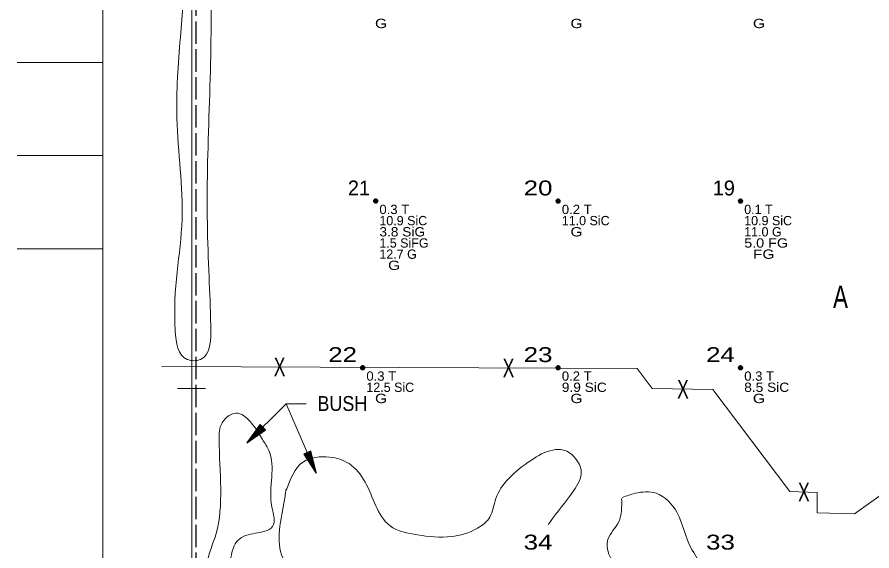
# Model space of a CAD drawing. Extents: x -496 to 480, y -450 to 700.
# Drawn here: x -496.1 to -37.5, y -87.1 to 199.3 of the extents above; entities that cross this region are included whole.
import ezdxf
from ezdxf.enums import TextEntityAlignment as Align

# ---------------------------------------------------------------- set-up
doc = ezdxf.new("R2010")
doc.units = 0
doc.header["$LTSCALE"] = 2
doc.linetypes.add('LONG_DASHED', pattern=[7.5, 6, -1.5])
for name, color, linetype, lineweight in [('1', 7, 'Continuous', 13), ('2', 7, 'Continuous', 35), ('3', 7, 'Continuous', 13), ('4', 7, 'Continuous', 25)]:
    doc.layers.add(name, color=color, linetype=linetype, lineweight=lineweight)

msp = doc.modelspace()

# ---------------------------------------------------------------- linework, layer by layer
at = {"layer": '1'}
for p, q in [((-402.391, 402.339), (-402.391, -402.333)), ((-450.017, 174.973), (-496.057, 174.973)), ((-450.017, 124.973), (-496.057, 124.973)), ((-450.017, 74.973), (-496.057, 74.973)), ((-395.017, -0.027), (-410.017, -0.027))]:
    msp.add_line(p, q, dxfattribs=at)
msp.add_lwpolyline([(449.983, -450.027), (449.983, 399.973), (449.983, 699.973), (-450.017, 699.973), (-450.017, 49.973), (-450.017, -450.027)], dxfattribs=at)
at = {"layer": '2', "linetype": 'LONG_DASHED', "lineweight": 25}
msp.add_line((-400, -400), (-400, 302.339), dxfattribs=at)
at = {"layer": '2'}
for centre in [(-303.709, 100.614), (-205.849, 100.614), (-107.989, 100.614), (-310.699, 11.214), (-205.849, 11.214), (-107.989, 11.214)]:
    msp.add_circle(centre, 1, dxfattribs=at)
for points in [[(-303.72, 101.501), (-302.989, 101.097), (-302.838, 100.248), (-303.523, 99.72), (-304.332, 99.951), (-304.618, 100.709), (-304.371, 101.271), (-303.798, 101.439), (-303.124, 100.945), (-303.141, 100.203), (-303.658, 99.945), (-304.18, 100.114), (-304.405, 100.76), (-303.821, 101.226), (-303.383, 100.692), (-303.422, 100.209), (-304.051, 100.344), (-303.905, 100.979), (-303.613, 100.428)], [(-205.86, 101.501), (-205.129, 101.097), (-204.978, 100.248), (-205.663, 99.72), (-206.472, 99.951), (-206.758, 100.709), (-206.511, 101.271), (-205.938, 101.439), (-205.264, 100.945), (-205.281, 100.203), (-205.798, 99.945), (-206.32, 100.114), (-206.545, 100.76), (-205.961, 101.226), (-205.523, 100.692), (-205.562, 100.209), (-206.191, 100.344), (-206.045, 100.979), (-205.753, 100.428)], [(-108, 101.501), (-107.269, 101.097), (-107.118, 100.248), (-107.803, 99.72), (-108.612, 99.951), (-108.898, 100.709), (-108.651, 101.271), (-108.078, 101.439), (-107.404, 100.945), (-107.421, 100.203), (-107.938, 99.945), (-108.46, 100.114), (-108.685, 100.76), (-108.101, 101.226), (-107.663, 100.692), (-107.702, 100.209), (-108.331, 100.344), (-108.185, 100.979), (-107.893, 100.428)], [(-310.71, 12.101), (-309.979, 11.697), (-309.828, 10.848), (-310.513, 10.32), (-311.322, 10.551), (-311.608, 11.309), (-311.361, 11.871), (-310.788, 12.039), (-310.114, 11.545), (-310.131, 10.803), (-310.648, 10.545), (-311.17, 10.714), (-311.395, 11.36), (-310.811, 11.826), (-310.373, 11.292), (-310.412, 10.809), (-311.041, 10.944), (-310.895, 11.579), (-310.603, 11.028)], [(-205.86, 12.101), (-205.129, 11.697), (-204.978, 10.848), (-205.663, 10.32), (-206.472, 10.551), (-206.758, 11.309), (-206.511, 11.871), (-205.938, 12.039), (-205.264, 11.545), (-205.281, 10.803), (-205.798, 10.545), (-206.32, 10.714), (-206.545, 11.36), (-205.961, 11.826), (-205.523, 11.292), (-205.562, 10.809), (-206.191, 10.944), (-206.045, 11.579), (-205.753, 11.028)], [(-108, 12.101), (-107.269, 11.697), (-107.118, 10.848), (-107.803, 10.32), (-108.612, 10.551), (-108.898, 11.309), (-108.651, 11.871), (-108.078, 12.039), (-107.404, 11.545), (-107.421, 10.803), (-107.938, 10.545), (-108.46, 10.714), (-108.685, 11.36), (-108.101, 11.826), (-107.663, 11.292), (-107.702, 10.809), (-108.331, 10.944), (-108.185, 11.579), (-107.893, 11.028)]]:
    msp.add_spline(points, degree=3, dxfattribs=at)
at = {"layer": '3'}
msp.add_lwpolyline([(-418.392, 11.933), (-163.468, 10.85), (-155.332, 0.015), (-122.789, -0.527), (-81.567, -55.245), (-66.922, -55.787), (-66.922, -66.622), (-46.854, -67.164), (-30.04, -55.245), (79.523, -55.245), (87.202, -45.019), (99.497, -44.943), (100.033, -35.45)], dxfattribs=at)
for points in [[(-407.583, 368.504), (-377.691, 369.409), (-355.045, 369.409), (-344.175, 368.504), (-328.776, 371.218), (-313.377, 372.123), (-278.956, 368.504), (-253.593, 366.695), (-220.983, 368.504), (-195.62, 369.409), (-113.189, 371.218), (-62.463, 366.695), (-15.36, 370.314), (129.573, 369.409), (163.088, 366.695), (215.626, 369.409), (283.563, 369.409), (313.456, 370.314), (344.254, 369.409), (357.841, 369.409), (358.747, 364.885), (359.653, 358.552), (346.971, 354.028), (317.985, 355.837), (282.658, 358.552), (167.617, 358.552), (86.999, 357.647), (29.026, 354.028), (-29.853, 357.647), (-94.167, 358.552), (-118.624, 356.742), (-177.503, 359.456), (-248.158, 354.932), (-325.153, 358.552), (-355.951, 354.932), (-383.126, 358.552), (-389.467, 354.932), (-393.996, 342.265), (-393.09, 244.549), (-392.184, 178.5), (-393.996, 113.356), (-393.996, 88.927), (-393.09, 59.974), (-392.184, 33.736), (-397.619, 15.64), (-404.866, 15.64), (-411.207, 31.021), (-407.583, 90.737), (-410.301, 145.024), (-408.489, 188.453), (-408.489, 262.645), (-411.207, 278.931), (-407.583, 312.408), (-409.395, 347.694), (-409.395, 353.123), (-415.736, 357.647)], [(-405.865, -94.67), (-400.768, -99.124), (-397.265, -100.078), (-394.398, -94.034), (-389.302, -77.808), (-387.709, -27.222), (-386.117, -18.314), (-377.517, -13.224), (-373.695, -15.133), (-364.458, -27.222), (-360.954, -33.267), (-359.361, -63.491), (-359.043, -73.99), (-363.183, -76.535), (-373.376, -78.762), (-377.517, -81.308), (-381.339, -90.534), (-379.746, -125.212), (-376.88, -132.211), (-377.517, -140.801), (-380.065, -160.845), (-383.25, -165.299), (-390.576, -166.571), (-392.345, -166.607)], [(-351.717, -54.583), (-342.48, -39.312), (-328.465, -36.767), (-317.954, -40.267), (-309.354, -50.129), (-303.621, -62.855), (-295.976, -73.672), (-281.325, -78.444), (-263.169, -79.399), (-249.155, -74.945), (-242.466, -68.9), (-239.28, -59.037), (-232.592, -48.538), (-220.169, -38.358), (-208.703, -32.949), (-202.97, -32.949), (-196.599, -37.403), (-193.414, -44.402), (-197.555, -54.901), (-210.295, -71.763), (-211.147, -73.024)], [(-222.064, -94.436), (-227.814, -98.806), (-246.925, -105.169), (-259.666, -109.305), (-274.317, -111.532), (-287.058, -110.895), (-297.251, -112.804), (-304.258, -119.167), (-314.132, -118.849), (-331.332, -110.895), (-342.161, -102.624), (-352.672, -92.443), (-352.991, -61.582), (-351.717, -53.947)], [(-171.436, -58.401), (-164.429, -56.174), (-153.281, -56.174), (-142.133, -66.355), (-133.851, -86.716), (-130.348, -95.942), (-136.4, -99.76), (-149.777, -100.078), (-165.066, -99.76), (-173.985, -95.624), (-179.081, -80.989), (-173.348, -71.445), (-171.755, -59.037)]]:
    msp.add_spline(points, degree=3, dxfattribs=at)
at = {"layer": '4', "lineweight": 13}
msp.add_line((-351.799, -8.187), (-335.577, -45.32), dxfattribs=at)
msp.add_lwpolyline([(-340.985, -8.187), (-351.799, -8.187), (-372.753, -29.116)], dxfattribs=at)
at = {"layer": '4'}
for points in [[(-372.753, -29.116), (-362.849, -22.051), (-365.676, -19.221)], [(-335.577, -45.32), (-338.549, -33.522), (-342.214, -35.124)]]:
    msp.add_lwpolyline(points, close=True, dxfattribs=at)
for points in [[(-363.002, -22.037), (-372.346, -28.711), (-365.675, -19.452), (-363.156, -21.945), (-371.825, -28.191), (-365.692, -19.711), (-363.383, -21.959), (-371.274, -27.641), (-365.675, -20.003), (-363.627, -21.899), (-370.634, -27.031), (-365.707, -20.309), (-363.935, -21.898), (-369.867, -26.297), (-365.661, -20.63), (-364.271, -21.867), (-369.042, -25.504), (-365.63, -21.057), (-364.622, -21.883), (-368.108, -24.662), (-365.691, -21.485), (-365.034, -21.929), (-367.068, -23.593), (-365.708, -22.018)], [(-338.618, -33.66), (-335.806, -44.793), (-341.998, -35.207), (-338.76, -33.77), (-336.101, -44.118), (-341.764, -35.317), (-338.829, -33.987), (-336.413, -43.405), (-341.486, -35.408), (-338.974, -34.192), (-336.748, -42.586), (-341.212, -35.549), (-339.087, -34.479), (-337.151, -41.605), (-340.897, -35.623), (-339.238, -34.78), (-337.59, -40.548), (-340.487, -35.75), (-339.351, -35.112), (-338.033, -39.372), (-340.112, -35.962), (-339.459, -35.513), (-338.65, -38.013), (-339.621, -36.173)]]:
    msp.add_lwpolyline(points, dxfattribs=at)

# ---------------------------------------------------------------- texts
at = {"layer": '2'}
for s, width, p in [('  G        ', 1.25, (-308.699, 193.364)), ('  G        ', 1.25, (-203.849, 193.364)), ('  G        ', 1.25, (-105.989, 193.364)), ('0.3 T      ', 1.05, (-301.709, 93.614)), ('0.2 T      ', 1.05, (-203.849, 93.614)), ('3.8 SiG    ', 1.1, (-301.709, 81.614)), ('  G        ', 1.25, (-203.849, 81.614)), ('5.0 FG     ', 1.15, (-105.989, 75.614)), ('  FG       ', 1.25, (-105.989, 69.614)), ('  G        ', 1.25, (-301.709, 63.614)), ('0.3 T      ', 1.05, (-308.699, 4.214)), ('0.2 T      ', 1.05, (-203.849, 4.214)), ('0.3 T      ', 1.05, (-105.989, 4.214)), ('9.9 SiC    ', 1.1, (-203.849, -1.786)), ('8.5 SiC    ', 1.1, (-105.989, -1.786)), ('  G        ', 1.25, (-308.699, -7.786)), ('  G        ', 1.25, (-203.849, -7.786)), ('  G        ', 1.25, (-105.989, -7.786))]:
    msp.add_text(s, height=5, dxfattribs=dict(at, width=width)).set_placement(p)
for s, p in [(' 21', (-306.709, 103.614)), (' 19', (-110.989, 103.614))]:
    msp.add_text(s, height=8, dxfattribs=at).set_placement(p, align=Align.RIGHT)
at = {"layer": '2', "width": 1.3}
for s, p in [(' 20', (-208.849, 103.614)), (' 22', (-313.699, 14.214)), (' 23', (-208.849, 14.214)), (' 24', (-110.989, 14.214)), (' 34', (-208.849, -86.361)), (' 33', (-110.989, -86.361))]:
    msp.add_text(s, height=8, dxfattribs=at).set_placement(p, align=Align.RIGHT)
at = {"layer": '2'}
for s, p in [('0.1 T      ', (-105.989, 93.614)), ('10.9 SiC   ', (-301.709, 87.614)), ('11.0 SiC   ', (-203.849, 87.614)), ('10.9 SiC   ', (-105.989, 87.614)), ('11.0 G     ', (-105.989, 81.614)), ('1.5 SiFG   ', (-301.709, 75.614)), ('12.7 G     ', (-301.709, 69.614)), ('12.5 SiC   ', (-308.699, -1.786))]:
    msp.add_text(s, height=5, dxfattribs=at).set_placement(p)
at = {"layer": '2', "width": 0.75}
msp.add_text('A', height=12, dxfattribs=at).set_placement((-54.349, 43.199), align=Align.CENTER)
at = {"layer": '3', "width": 0.7}
for p in [(-355.238, 6.645), (-232.439, 6.009), (-138.864, -5.328), (-74.005, -60.539)]:
    msp.add_text('X', height=10, dxfattribs=at).set_placement(p, align=Align.CENTER)
at = {"layer": '4', "width": 0.9}
msp.add_text('BUSH', height=8, dxfattribs=at).set_placement((-321.565, -11.996), align=Align.CENTER)

doc.saveas('drawing.dxf')
